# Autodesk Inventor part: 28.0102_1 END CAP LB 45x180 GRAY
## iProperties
Created: 2007-01
Part Number: 28.0102_1 END CAP LB 45x180 GRAY
Document SubType Name: Modeling
Designer: Andy Moles
Material: ABS Plastic
Density: 1.06 g/cm^3
Author: Andy Moles
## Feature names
1. Extrusion1
2. Fillet1
3. Fillet2
4. Extrusion2
